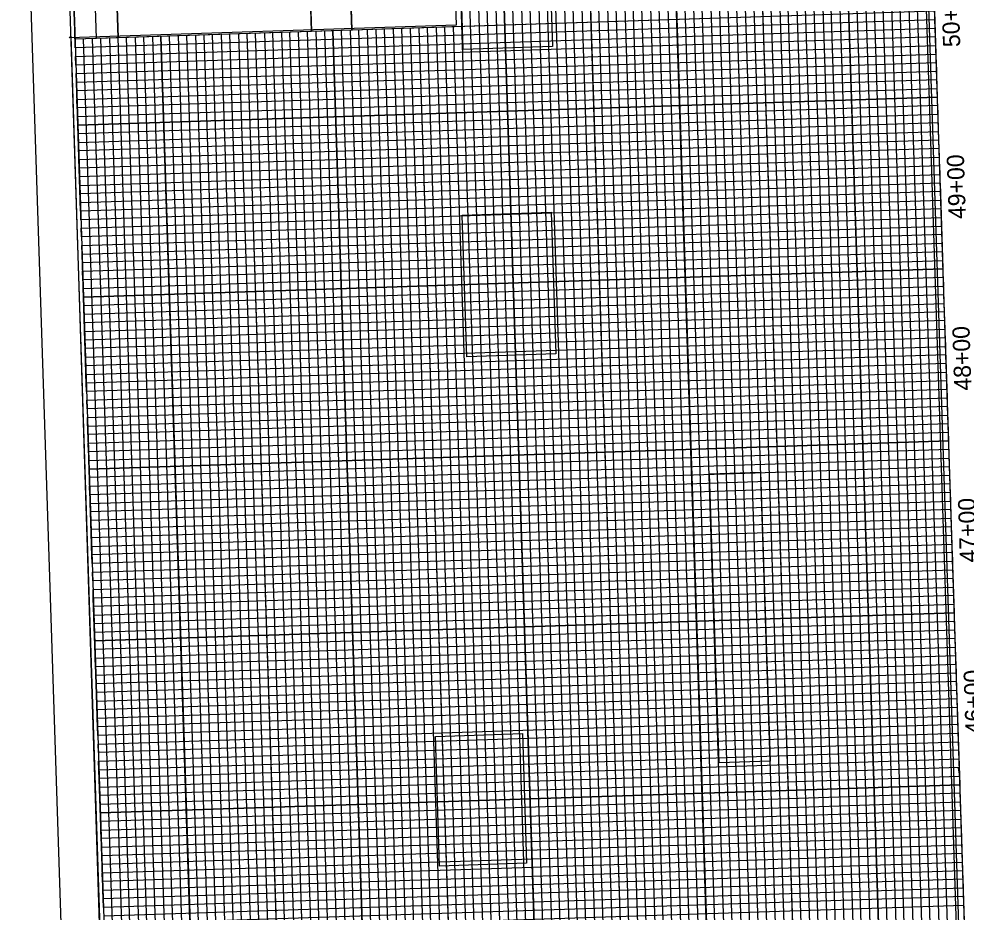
# Model space of a CAD drawing. Extents: x 1627318 to 1628473, y 762308 to 764226.
# Drawn here: x 1627318 to 1627868, y 763268 to 763787 of the extents above; entities that cross this region are included whole.
import ezdxf

# ---------------------------------------------------------------- set-up
doc = ezdxf.new("R2010")
doc.units = 0
for name, color, linetype in [('Exist Vertical Profile Horizontal Axis Label Major', 7, 'Continuous'), ('Old_Level_2', 7, 'Continuous'), ('Prop Grid Mask', 7, 'Continuous'), ('Sheet DOT Grid CELL', 7, 'Continuous'), ('Sheet Layout Profile Border Port 1', 7, 'Continuous'), ('Sheet Plot Border Inside CELL', 7, 'Continuous'), ('Sheet Plot Border Outside CELL', 7, 'Continuous'), ('Sheet Profile CELL', 7, 'Continuous'), ('Sheet Profile Grid Major CELL', 7, 'Continuous'), ('Sheet Profile Grid Middle CELL', 7, 'Continuous'), ('Sheet Profile Grid Minor CELL', 7, 'Continuous'), ('Sheet Sticker Exception Certification CELL', 7, 'Continuous')]:
    doc.layers.add(name, color=color, linetype=linetype)

msp = doc.modelspace()

# ---------------------------------------------------------------- linework, layer by layer
at = {"layer": 'Old_Level_2'}
msp.add_lwpolyline([(1627511.12, 763780.74), (1627504.58, 763980.62), (1627568.5, 763982.71), (1627575.04, 763782.83)], close=True, dxfattribs=at)
at = {"layer": 'Prop Grid Mask'}
for points in [[(1627575.85, 763769.46), (1627573.42, 763843.69), (1627625.24, 763845.39), (1627627.67, 763771.15)], [(1627577.82, 763590.85), (1627575.12, 763673.26), (1627627.03, 763674.96), (1627629.73, 763592.55)], [(1627724.55, 763354.81), (1627719.06, 763522.73), (1627748.7, 763523.7), (1627754.19, 763355.78)], [(1627562.08, 763294.71), (1627559.61, 763370.11), (1627610.21, 763371.77), (1627612.68, 763296.37)]]:
    msp.add_lwpolyline(points, close=True, dxfattribs=at)
at = {"layer": 'Sheet DOT Grid CELL'}
for p, q in [((1627643.46, 763985.17), (1627692.5, 762485.97)), ((1627693.43, 763986.81), (1627742.47, 762487.61)), ((1627743.4, 763988.44), (1627792.44, 762489.24)), ((1627793.38, 763990.08), (1627842.42, 762490.88)), ((1627593.48, 763983.54), (1627642.52, 762484.34)), ((1627849.89, 763791.82), (1627487.63, 763779.97)), ((1627550.05, 763781.96), (1627592.55, 762482.7)), ((1627400.13, 763777.06), (1627442.63, 762477.8)), ((1627450.11, 763778.69), (1627492.6, 762479.43)), ((1627500.08, 763780.37), (1627542.58, 762481.07)), ((1627851.52, 763741.84), (1627351.79, 763725.5)), ((1627853.16, 763691.87), (1627353.43, 763675.52)), ((1627854.79, 763641.9), (1627355.06, 763625.55)), ((1627856.43, 763591.92), (1627356.7, 763575.58)), ((1627858.06, 763541.95), (1627358.33, 763525.6)), ((1627859.7, 763491.98), (1627359.96, 763475.63)), ((1627861.33, 763442), (1627361.6, 763425.66)), ((1627862.97, 763392.03), (1627363.23, 763375.68)), ((1627864.6, 763342.06), (1627364.87, 763325.71)), ((1627866.24, 763292.08), (1627366.5, 763275.74))]:
    msp.add_line(p, q, dxfattribs=at)
at = {"layer": 'Sheet Layout Profile Border Port 1'}
msp.add_lwpolyline([(1627387.69, 762527.01), (1627887.42, 762543.36), (1627841.65, 763942.61), (1627566.8, 763933.62), (1627571.7, 763783.65), (1627346.82, 763776.3), (1627347.71, 763777.21)], close=True, dxfattribs=at)
msp.add_lwpolyline([(1627551.99, 762531.4), (1627890.76, 762542.49), (1627844.99, 763941.74), (1627570.13, 763932.75)], dxfattribs=at)
at = {"layer": 'Sheet Plot Border Inside CELL'}
msp.add_lwpolyline([(1628449.68, 762356.66), (1628395.2, 764022.27), (1627340.66, 763987.77), (1627395.14, 762322.16)], close=True, dxfattribs=at)
at = {"layer": 'Sheet Plot Border Outside CELL'}
msp.add_lwpolyline([(1628472.54, 762344.4), (1628416.96, 764043.49), (1627317.55, 764007.53), (1627373.13, 762308.44)], close=True, dxfattribs=at)
at = {"layer": 'Sheet Profile CELL'}
for p, q in [((1627892.39, 762492.51), (1627843.35, 763991.71)), ((1627362.7, 763775.83), (1627356.16, 763975.77))]:
    msp.add_line(p, q, dxfattribs=at)
for points in [[(1627343.62, 763975.36), (1627392.66, 762476.17), (1628442.1, 762510.49), (1628393.06, 764009.69)], [(1627350.16, 763775.42), (1627343.62, 763975.36), (1627368.66, 763976.18), (1627375.2, 763776.24)], [(1627375.2, 763776.24), (1627371.92, 763876.24), (1627484.36, 763879.91), (1627487.64, 763779.92)]]:
    msp.add_lwpolyline(points, close=True, dxfattribs=at)
at = {"layer": 'Sheet Profile Grid Major CELL'}
for points in [[(1627643.46, 763985.17), (1627692.5, 762485.97), (1627742.47, 762487.61), (1627693.43, 763986.81)], [(1627743.4, 763988.44), (1627792.44, 762489.24), (1627792.44, 762489.24), (1627842.42, 762490.88), (1627793.38, 763990.08)], [(1627550.05, 763782.01), (1627592.55, 762482.7), (1627642.52, 762484.34), (1627593.48, 763983.54)], [(1627867.87, 763242.11), (1627866.24, 763292.08), (1627366.5, 763275.74), (1627364.87, 763325.71), (1627864.6, 763342.06), (1627862.97, 763392.03), (1627363.23, 763375.68), (1627361.6, 763425.66), (1627861.33, 763442), (1627859.7, 763491.98), (1627359.96, 763475.63), (1627358.33, 763525.6), (1627858.06, 763541.95), (1627856.43, 763591.92), (1627356.7, 763575.58), (1627355.06, 763625.55), (1627854.79, 763641.9), (1627853.16, 763691.87), (1627353.43, 763675.52), (1627351.79, 763725.5), (1627851.52, 763741.84), (1627849.89, 763791.82), (1627350.16, 763775.47), (1627349.3, 763801.76)], [(1627442.63, 762477.8), (1627400.13, 763777.11)], [(1627450.1, 763778.74), (1627492.6, 762479.43), (1627542.58, 762481.07), (1627500.08, 763780.37)]]:
    msp.add_lwpolyline(points, dxfattribs=at)
at = {"layer": 'Sheet Profile Grid Middle CELL'}
msp.add_line((1627417.64, 762476.98), (1627375.15, 763776.24), dxfattribs=at)
for points in [[(1627818.36, 763990.89), (1627867.4, 762491.69)], [(1627618.47, 763984.35), (1627667.51, 762485.16), (1627717.48, 762486.79), (1627668.44, 763985.99)], [(1627718.42, 763987.62), (1627767.46, 762488.43), (1627817.43, 762490.06), (1627768.39, 763989.26)], [(1627867.05, 763267.1), (1627865.42, 763317.07), (1627365.69, 763300.72), (1627364.05, 763350.7), (1627863.78, 763367.04), (1627862.15, 763417.02), (1627362.42, 763400.67), (1627360.78, 763450.64), (1627860.51, 763466.99), (1627858.88, 763516.96), (1627359.15, 763500.62), (1627357.51, 763550.59), (1627857.25, 763566.94), (1627855.61, 763616.91), (1627355.88, 763600.56), (1627354.24, 763650.54), (1627853.98, 763666.88), (1627852.34, 763716.86), (1627352.61, 763700.51), (1627350.97, 763750.48), (1627850.71, 763766.83), (1627849.07, 763816.8), (1627574.22, 763807.81)], [(1627525.07, 763781.14), (1627567.56, 762481.89), (1627617.54, 762483.52), (1627574.22, 763807.81)], [(1627425.12, 763777.92), (1627467.62, 762478.62), (1627517.59, 762480.25), (1627475.09, 763779.56)]]:
    msp.add_lwpolyline(points, dxfattribs=at)
at = {"layer": 'Sheet Profile Grid Minor CELL'}
for p, q in [((1627815, 763940.76), (1627860.77, 762541.5)), ((1627870.77, 762541.83), (1627825, 763941.08)), ((1627829.99, 763941.25), (1627875.76, 762541.99)), ((1627880.76, 762542.16), (1627834.99, 763941.41)), ((1627695.86, 762536.11), (1627650.09, 763935.36)), ((1627655.09, 763935.53), (1627700.86, 762536.27)), ((1627705.85, 762536.44), (1627660.08, 763935.69)), ((1627665.08, 763935.85), (1627710.85, 762536.6)), ((1627720.85, 762536.93), (1627675.08, 763936.18)), ((1627680.07, 763936.34), (1627725.84, 762537.09)), ((1627730.84, 762537.25), (1627685.07, 763936.51)), ((1627690.07, 763936.67), (1627735.84, 762537.42)), ((1627745.83, 762537.74), (1627700.06, 763937)), ((1627705.06, 763937.16), (1627750.83, 762537.91)), ((1627755.83, 762538.07), (1627710.06, 763937.32)), ((1627715.06, 763937.49), (1627760.82, 762538.24)), ((1627770.82, 762538.56), (1627725.05, 763937.81)), ((1627730.05, 763937.98), (1627775.82, 762538.73)), ((1627735.04, 763938.14), (1627780.81, 762538.89)), ((1627740.04, 763938.3), (1627785.81, 762539.05)), ((1627795.81, 762539.38), (1627750.04, 763938.63)), ((1627755.03, 763938.79), (1627800.8, 762539.54)), ((1627805.8, 762539.71), (1627760.03, 763938.96)), ((1627765.03, 763939.12), (1627810.8, 762539.87)), ((1627820.79, 762540.2), (1627775.02, 763939.45)), ((1627780.02, 763939.61), (1627825.79, 762540.36)), ((1627830.79, 762540.52), (1627785.02, 763939.78)), ((1627790.02, 763939.94), (1627835.78, 762540.69)), ((1627845.78, 762541.01), (1627800.01, 763940.27)), ((1627805.01, 763940.43), (1627850.78, 762541.18)), ((1627855.77, 762541.34), (1627810, 763940.59)), ((1627580.13, 763933.07), (1627625.9, 762533.82)), ((1627630.89, 762533.99), (1627585.12, 763933.24)), ((1627590.12, 763933.4), (1627635.89, 762534.15)), ((1627645.89, 762534.48), (1627600.12, 763933.73)), ((1627605.11, 763933.89), (1627650.88, 762534.64)), ((1627655.88, 762534.8), (1627610.11, 763934.05)), ((1627615.11, 763934.22), (1627660.88, 762534.97)), ((1627670.87, 762535.29), (1627625.1, 763934.54)), ((1627630.1, 763934.71), (1627675.87, 762535.46)), ((1627680.87, 762535.62), (1627635.1, 763934.87)), ((1627640.1, 763935.03), (1627685.86, 762535.78)), ((1627535.06, 763781.47), (1627575.92, 762532.19)), ((1627580.92, 762532.35), (1627540.06, 763781.63)), ((1627560.05, 763782.29), (1627600.91, 762533)), ((1627605.91, 762533.17), (1627565.04, 763782.45)), ((1627396.02, 762526.3), (1627355.15, 763775.63)), ((1627360.15, 763775.8), (1627401.37, 762526.48)), ((1627406.01, 762526.63), (1627365.15, 763775.96)), ((1627485.09, 763779.83), (1627525.95, 762530.55)), ((1627490.08, 763780.05), (1627530.95, 762530.72)), ((1627495.08, 763780.21), (1627535.94, 762530.88)), ((1627545.94, 762531.21), (1627505.07, 763780.54)), ((1627510.07, 763780.7), (1627550.94, 762531.37)), ((1627555.93, 762531.53), (1627515.07, 763780.81))]:
    msp.add_line(p, q, dxfattribs=at)
for points in [[(1627839.99, 763941.57), (1627885.76, 762542.32)], [(1627570.04, 763782.61), (1627610.9, 762533.33), (1627620.9, 762533.66), (1627575.13, 763932.91)], [(1627853.49, 763681.88), (1627853.32, 763686.87), (1627353.59, 763670.53), (1627353.26, 763680.52), (1627853, 763696.87), (1627852.83, 763701.86), (1627353.1, 763685.52), (1627352.94, 763690.52), (1627852.67, 763706.86), (1627852.51, 763711.86), (1627352.77, 763695.51), (1627352.45, 763705.51), (1627852.18, 763721.85), (1627852.01, 763726.85), (1627352.28, 763710.51), (1627352.12, 763715.5), (1627851.85, 763731.85), (1627851.69, 763736.85), (1627351.96, 763720.5), (1627351.63, 763730.49), (1627851.36, 763746.84), (1627851.2, 763751.84), (1627351.46, 763735.49), (1627351.3, 763740.49), (1627851.03, 763756.84), (1627850.87, 763761.83), (1627351.14, 763745.49), (1627350.81, 763755.48), (1627850.54, 763771.83), (1627850.38, 763776.82), (1627350.65, 763760.48), (1627350.48, 763765.48), (1627850.22, 763781.82), (1627850.05, 763786.82), (1627350.32, 763770.47), (1627349.99, 763780.47)], [(1627520.07, 763780.98), (1627560.93, 762531.7), (1627570.93, 762532.02), (1627530.06, 763781.31)], [(1627545.05, 763781.8), (1627585.92, 762532.51), (1627595.91, 762532.84), (1627555.05, 763782.12)], [(1627370.15, 763776.12), (1627411.01, 762526.79), (1627421.01, 762527.12), (1627380.14, 763776.45)], [(1627385.14, 763776.56), (1627426, 762527.28), (1627431, 762527.45), (1627390.14, 763776.78)], [(1627395.13, 763776.94), (1627436, 762527.61), (1627445.99, 762527.94), (1627405.13, 763777.27)], [(1627410.12, 763777.43), (1627450.99, 762528.1), (1627455.99, 762528.26), (1627415.12, 763777.6)], [(1627420.12, 763777.76), (1627460.99, 762528.43), (1627470.98, 762528.75), (1627430.11, 763778.09)], [(1627435.11, 763778.25), (1627475.98, 762528.92), (1627480.97, 762529.08), (1627440.11, 763778.41)], [(1627445.11, 763778.58), (1627485.97, 762529.24), (1627495.97, 762529.57), (1627455.1, 763778.9)], [(1627460.2, 763779.07), (1627501.06, 762529.84), (1627505.96, 762530), (1627465.1, 763779.23)], [(1627470.09, 763779.39), (1627510.96, 762530.06), (1627520.95, 762530.39), (1627480.09, 763779.72)], [(1627863.46, 763377.04), (1627363.72, 763360.69), (1627363.56, 763365.69), (1627863.29, 763382.04), (1627863.13, 763387.03), (1627363.4, 763370.69), (1627363.07, 763380.68), (1627862.8, 763397.03), (1627862.64, 763402.03), (1627362.91, 763385.68), (1627362.74, 763390.68), (1627862.48, 763407.02), (1627862.31, 763412.02), (1627362.58, 763395.67), (1627362.25, 763405.67), (1627861.99, 763422.01), (1627861.82, 763427.01), (1627362.09, 763410.67), (1627361.93, 763415.66), (1627861.66, 763432.01), (1627861.5, 763437.01), (1627361.76, 763420.66), (1627361.44, 763430.66), (1627861.17, 763447), (1627861.01, 763452), (1627361.27, 763435.65), (1627361.11, 763440.65), (1627860.84, 763457), (1627860.68, 763461.99), (1627360.95, 763445.65), (1627360.62, 763455.64), (1627860.35, 763471.99), (1627860.19, 763476.99), (1627360.46, 763460.64), (1627360.29, 763465.64), (1627860.02, 763481.98), (1627859.86, 763486.98), (1627360.13, 763470.63), (1627359.8, 763480.63), (1627859.53, 763496.97), (1627859.37, 763501.97), (1627359.64, 763485.63), (1627359.47, 763490.62), (1627859.21, 763506.97), (1627859.04, 763511.97), (1627359.31, 763495.62), (1627358.98, 763505.62), (1627858.72, 763521.96), (1627858.55, 763526.96), (1627358.82, 763510.61), (1627358.66, 763515.61), (1627858.39, 763531.96), (1627858.23, 763536.95), (1627358.49, 763520.61), (1627358.17, 763530.6), (1627857.9, 763546.95), (1627857.74, 763551.95), (1627358, 763535.6), (1627357.84, 763540.6), (1627857.57, 763556.94), (1627857.41, 763561.94), (1627357.68, 763545.59), (1627357.35, 763555.59), (1627857.08, 763571.93), (1627856.92, 763576.93), (1627357.19, 763560.59), (1627357.02, 763565.58), (1627856.76, 763581.93), (1627856.59, 763586.93), (1627356.86, 763570.58), (1627356.53, 763580.57), (1627856.26, 763596.92), (1627856.1, 763601.92), (1627356.37, 763585.57), (1627356.21, 763590.57), (1627855.94, 763606.92), (1627855.77, 763611.91), (1627356.04, 763595.57), (1627355.71, 763605.56), (1627855.45, 763621.91), (1627855.28, 763626.91), (1627355.55, 763610.56), (1627355.39, 763615.56), (1627855.12, 763631.9), (1627854.96, 763636.9), (1627355.22, 763620.55), (1627354.9, 763630.55), (1627854.63, 763646.89), (1627854.47, 763651.89), (1627354.73, 763635.55), (1627354.57, 763640.54), (1627854.3, 763656.89), (1627854.14, 763661.89), (1627354.41, 763645.54), (1627354.08, 763655.53), (1627853.81, 763671.88), (1627853.65, 763676.88), (1627353.92, 763660.53), (1627353.75, 763665.53), (1627853.49, 763681.88)], [(1627366.83, 763265.74), (1627866.56, 763282.09), (1627866.4, 763287.09), (1627366.67, 763270.74), (1627366.34, 763280.74), (1627866.07, 763297.08), (1627865.91, 763302.08), (1627366.18, 763285.73), (1627366.01, 763290.73), (1627865.75, 763307.08), (1627865.58, 763312.07), (1627365.85, 763295.73), (1627365.52, 763305.72), (1627865.26, 763322.07), (1627865.09, 763327.07), (1627365.36, 763310.72), (1627365.2, 763315.72), (1627864.93, 763332.06), (1627864.76, 763337.06), (1627365.03, 763320.71), (1627364.71, 763330.71), (1627864.44, 763347.05), (1627863.73, 763351.73), (1627864.27, 763352.05), (1627364.54, 763335.71), (1627364.38, 763340.7), (1627864.11, 763357.05), (1627863.95, 763362.05), (1627364.21, 763345.7), (1627363.89, 763355.7), (1627863.62, 763372.04), (1627863.46, 763377.04)], [(1627367.16, 763255.75), (1627866.89, 763272.09), (1627866.73, 763277.09), (1627366.99, 763260.75)]]:
    msp.add_lwpolyline(points, dxfattribs=at)
at = {"layer": 'Sheet Sticker Exception Certification CELL'}
for p, q in [((1627487.64, 763779.92), (1627481.1, 763979.85)), ((1627487.64, 763779.92), (1627481.1, 763979.85)), ((1627504.58, 763980.62), (1627511.12, 763780.69)), ((1627504.58, 763980.62), (1627511.12, 763780.69)), ((1627511.12, 763780.69), (1627487.64, 763779.92)), ((1627511.12, 763780.69), (1627487.64, 763779.92))]:
    msp.add_line(p, q, dxfattribs=at)

# ---------------------------------------------------------------- texts
at = {"layer": 'Exist Vertical Profile Horizontal Axis Label Major'}
for s, p in [('50+00', (1627864.77, 763771.05)), ('49+00', (1627868.04, 763671.12)), ('48+00', (1627871.3, 763571.32)), ('47+00', (1627874.57, 763471.41)), ('46+00', (1627877.84, 763371.49))]:
    msp.add_text(s, height=10, rotation=91.8735, dxfattribs=at).set_placement(p)

doc.saveas('drawing.dxf')
